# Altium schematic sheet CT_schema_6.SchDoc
size 287 x 211 mm
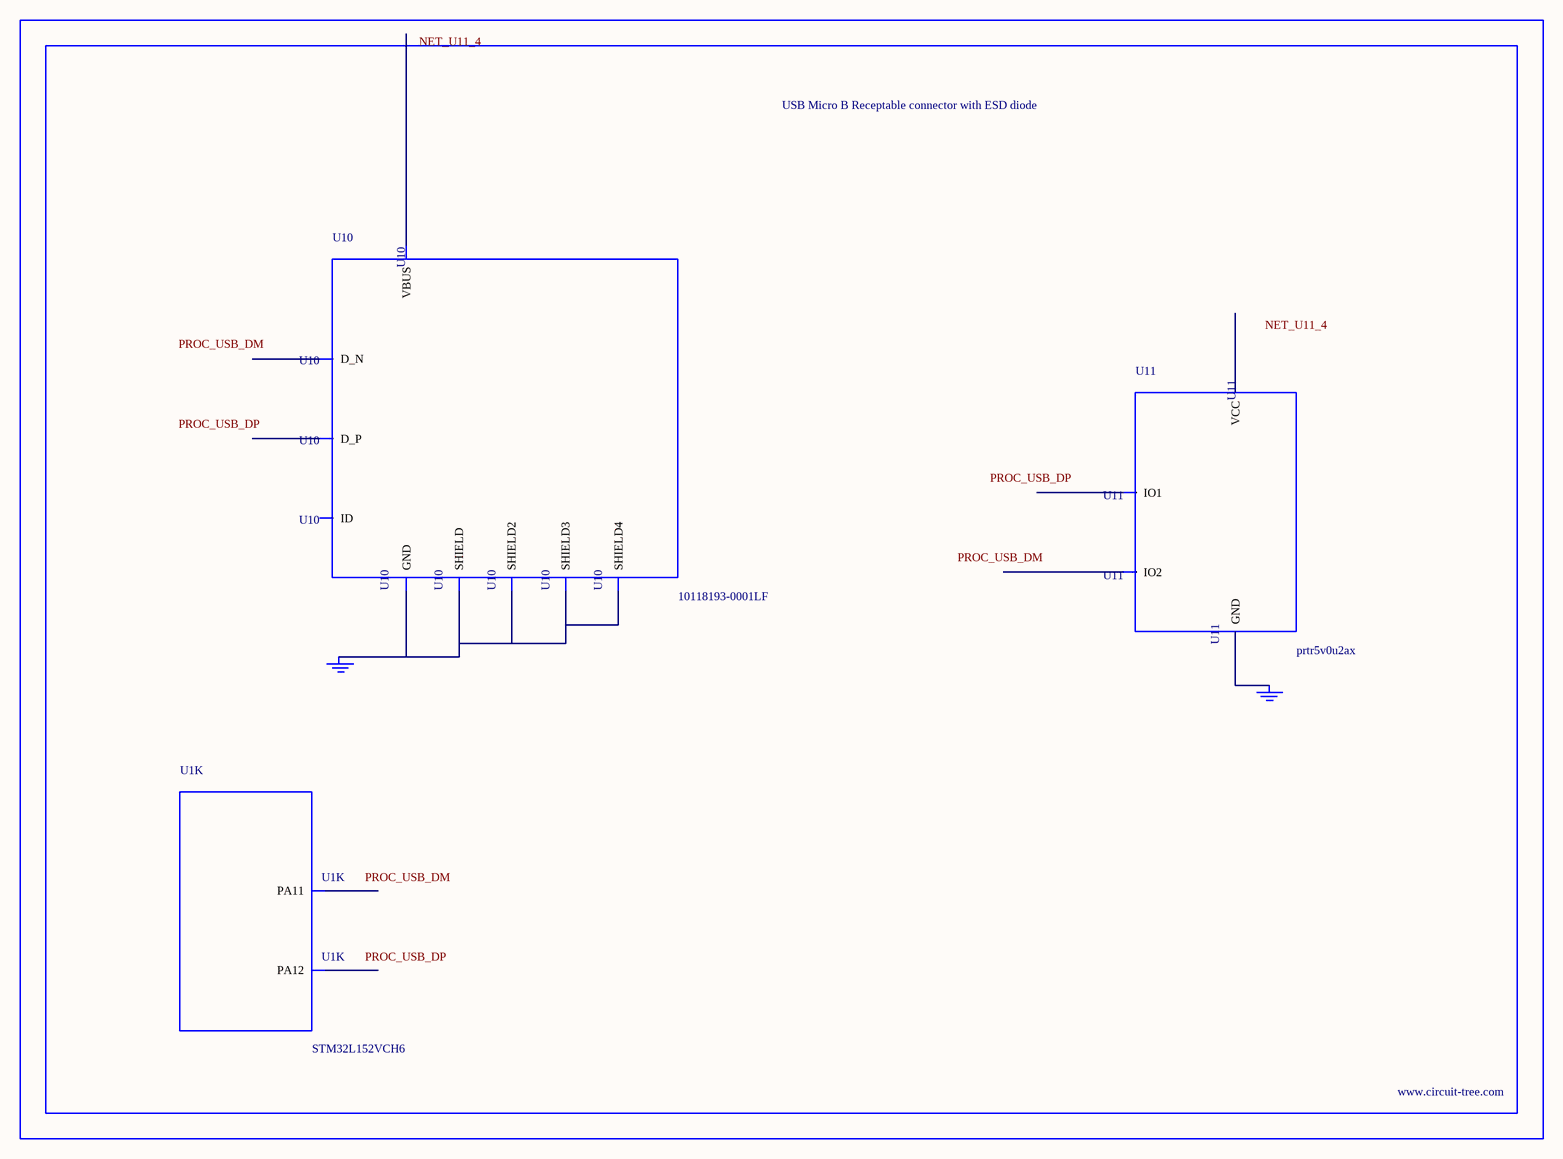
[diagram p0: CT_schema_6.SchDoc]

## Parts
BORDER5  (no value)
GND_INSTANCE_5_0  (no value)
GND_INSTANCE_5_1  (no value)
U1  STM32L152VCH6  [UFBGA100]  (part K of 11)
U10  10118193-0001LF  [FCI_10118193-0001LF]
U11  prtr5v0u2ax  [SOT143B]

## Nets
NetGND_INSTANCE_5_0_0: GND_INSTANCE_5_0.0(GND) U10.5(GND) U10.6(SHIELD) U10.7(SHIELD2) U10.8(SHIELD3) U10.9(SHIELD4)
NetGND_INSTANCE_5_1_0: GND_INSTANCE_5_1.0(GND) U11.1(GND)

Not connected (* = marked no-connect by the designer): U1 A12(PA12) B12(PA11); U10 1(VBUS) 2(D_N) 3(D_P) 4(ID); U11 2(IO1) 3(IO2) 4(VCC)

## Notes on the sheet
- Labels drawn without touching a wire or pin: NET_U11_4, PROC_USB_DM, PROC_USB_DP

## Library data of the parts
BORDER5 = BORDER_PAGE5
GND_INSTANCE_5_0 GND_INSTANCE_5_1 = GND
